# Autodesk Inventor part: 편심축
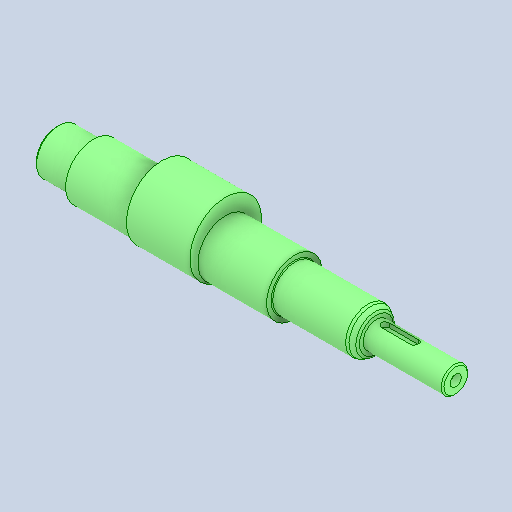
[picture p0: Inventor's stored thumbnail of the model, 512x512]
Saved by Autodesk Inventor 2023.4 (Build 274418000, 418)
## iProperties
Created: 2024-09
Part Number: 편심축
Material: 강철, 탄소
Document SubType Name: Modeling
Designer: EDU
Density: 7.85 g/cm^3
Appearance: 기본값
Author: jhkim
Sending System: Autodesk Inventor 2025
Preprocessor: ST-DEVELOPER v20
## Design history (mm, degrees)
feature "솔리드1"
node "솔리드2"
